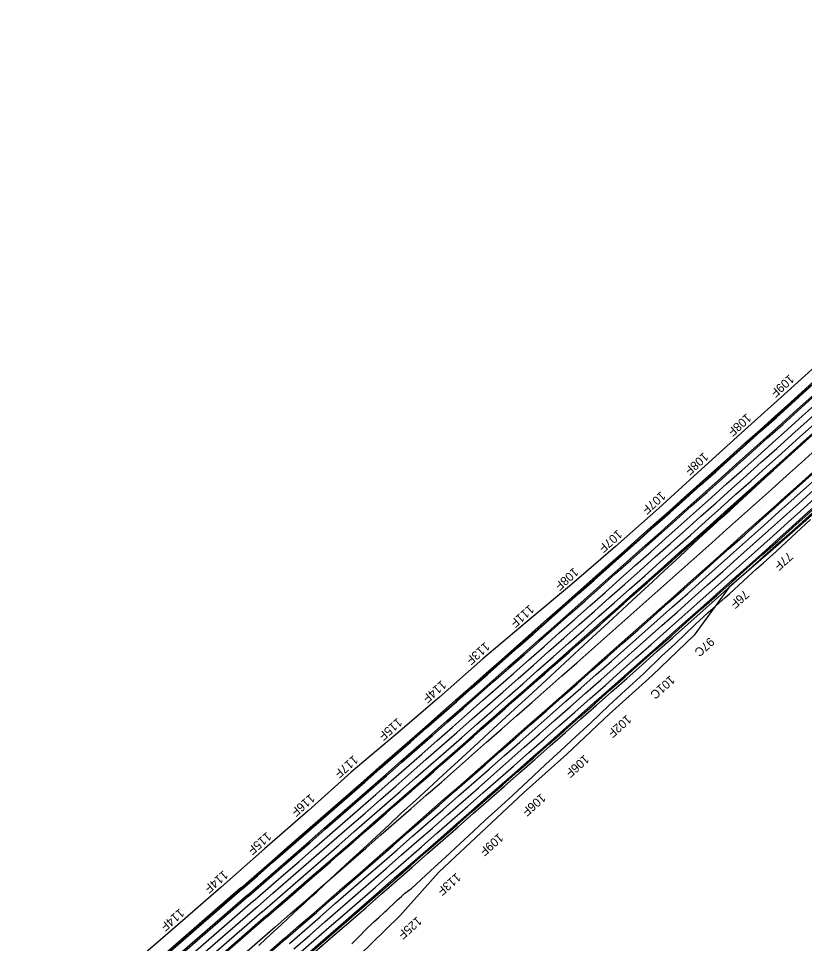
# Model space of a CAD drawing. Extents: x 2163396 to 2173129, y 605545 to 614595.
# Drawn here: x 2169556 to 2170912, y 611691 to 613286 of the extents above; entities that cross this region are included whole.
import ezdxf

# ---------------------------------------------------------------- set-up
doc = ezdxf.new("R2010")
doc.units = 0
for name, color, linetype in [('RD_PD_AsphRem', 7, 'Continuous'), ('RD_PD_CstnLmt', 7, 'Continuous'), ('RD_PD_EarthShd', 7, 'Continuous'), ('RD_PD_Final_LnLine', 7, 'Continuous'), ('RD_PD_Final_TrvlWay', 7, 'Continuous'), ('RD_PD_GR', 7, 'Continuous'), ('RD_PD_MedBWall', 7, 'Continuous'), ('RD_PD_TX_CstnLmt', 7, 'Continuous')]:
    doc.layers.add(name, color=color, linetype=linetype)

msp = doc.modelspace()

# ---------------------------------------------------------------- linework, layer by layer
at = {"layer": 'RD_PD_AsphRem'}
for points in [[(2169970.4, 611688.1), (2169983, 611699.5), (2169997.2, 611712.6), (2170008.5, 611723), (2170019.8, 611733.5), (2170031.8, 611744.5), (2170049.2, 611760.8), (2170061.5, 611772.2), (2170070.1, 611780.1), (2170083.4, 611792.3), (2170103.4, 611811.3), (2170127.9, 611833.7), (2170150.2, 611854), (2170173.7, 611876), (2170195.2, 611895.8), (2170216.4, 611915.9), (2170241.1, 611938.1), (2170263.7, 611959.3), (2170288.5, 611982.2), (2170314.6, 612005.9), (2170342.2, 612031.3), (2170367.1, 612054.4), (2170389.4, 612074.8), (2170412.4, 612095.8), (2170435.7, 612117.3), (2170458.6, 612138.6), (2170481.9, 612160), (2170507.1, 612183.4), (2170530.6, 612205), (2170552.9, 612225.7), (2170580.4, 612251), (2170606.6, 612275.4), (2170629.3, 612296.6), (2170649.7, 612315.1), (2170669.9, 612334), (2170689.8, 612352.3), (2170706.1, 612367.4), (2170720.5, 612381.2), (2170736.9, 612396.3), (2170753.8, 612411.6), (2170769.4, 612425.8), (2170782.9, 612438.2), (2170812.1, 612465), (2170836.2, 612487.5), (2170858.2, 612507.6)], [(2170858.2, 612507.6), (2170858.2, 612507.6)], [(2170131.1, 611690.6), (2170136.4, 611696), (2170145.4, 611705.4), (2170153.4, 611713.6), (2170158.7, 611718.7), (2170164.7, 611723.9), (2170167.2, 611726.7), (2170169.8, 611729), (2170176.8, 611735.6), (2170188.2, 611745.9), (2170191.5, 611748.9), (2170196.3, 611753.5), (2170202.7, 611759.6), (2170210.1, 611766.4), (2170216.6, 611772.2), (2170222.3, 611777.9), (2170230.4, 611783.9), (2170233.9, 611786.4), (2170266.8, 611816.4), (2170292.8, 611840.3), (2170317.3, 611862.9), (2170341.2, 611885.4), (2170360.9, 611903.8), (2170382.6, 611923.8), (2170408.1, 611946.8), (2170434.8, 611971.4), (2170465.3, 612000.1), (2170491.7, 612024.3), (2170516.8, 612047.9), (2170543.6, 612072.4), (2170574.5, 612101.7), (2170603, 612127.9), (2170634.6, 612157), (2170665.4, 612186.5), (2170688.6, 612208.2), (2170722.9, 612240.6), (2170745.9, 612262.1), (2170758.3, 612272.9), (2170775.1, 612287.9), (2170782.4, 612294.5), (2170813.8, 612323.5), (2170829.1, 612337.2), (2170841.3, 612347.9), (2170863.1, 612367.4), (2170897.7, 612400.1), (2170922.2, 612422.5)], [(2169984, 611736.6), (2169723.7, 611510.7), (2169722.6, 611509.8)]]:
    msp.add_lwpolyline(points, dxfattribs=at)
for radius, end in [(73072, 312.719474), (72976, 311.868675)]:
    msp.add_arc((2122152.2, 666851.2), radius, 310.953509, end, dxfattribs=at)
at = {"layer": 'RD_PD_CstnLmt'}
for p, q in [((2170956.3, 612710.4), (2170882.2, 612643.4)), ((2170882.2, 612643.4), (2170808.4, 612576.2)), ((2170808.4, 612576.2), (2170734.3, 612509.2)), ((2170734.3, 612509.2), (2170660.6, 612441.8)), ((2170660.6, 612441.8), (2170585.8, 612375.7)), ((2170933, 612437.1), (2170857.7, 612371.2)), ((2170585.8, 612375.7), (2170510.2, 612310.4)), ((2170857.7, 612371.2), (2170782.1, 612305.6)), ((2170510.2, 612310.4), (2170433.6, 612246.3)), ((2170782.1, 612305.6), (2170721.4, 612223.2)), ((2170433.6, 612246.3), (2170357.2, 612182)), ((2170721.4, 612223.2), (2170649.2, 612153.7)), ((2170357.2, 612182), (2170282.2, 612116.1)), ((2170649.2, 612153.7), (2170575, 612086.5)), ((2170282.2, 612116.1), (2170206.2, 612051.4)), ((2170575, 612086.5), (2170502.1, 612017.7)), ((2170206.2, 612051.4), (2170130.1, 611986.7)), ((2170502.1, 612017.7), (2170427.3, 611951.1)), ((2170130.1, 611986.7), (2170055.5, 611920.3)), ((2170427.3, 611951.1), (2170354.2, 611882.5)), ((2170055.5, 611920.3), (2169980.4, 611854.5)), ((2170354.2, 611882.5), (2170281, 611814.1)), ((2169980.4, 611854.5), (2169905.7, 611788.2)), ((2170281, 611814.1), (2170213.6, 611739)), ((2169905.7, 611788.2), (2169830.2, 611722.7)), ((2170213.6, 611739), (2170141.8, 611668.9)), ((2169830.2, 611722.7), (2169754.5, 611657.3))]:
    msp.add_line(p, q, dxfattribs=at)
at = {"layer": 'RD_PD_EarthShd'}
for p, q in [((2169939.9, 611787.5), (2169556.2, 611454.5)), ((2169984, 611736.6), (2169600.3, 611403.7)), ((2170015.5, 611700.4), (2169631.8, 611367.4))]:
    msp.add_line(p, q, dxfattribs=at)
for radius, end in [(72908.7, 312.719474), (73075.8, 312.719474), (72976, 312.614643), (73024, 312.612747)]:
    msp.add_arc((2122152.2, 666851.2), radius, 310.953509, end, dxfattribs=at)
at = {"layer": 'RD_PD_Final_LnLine'}
for p, q in [((2169941.8, 611785.2), (2169558.2, 611452.2)), ((2169951, 611774.7), (2169567.3, 611441.7)), ((2169960.4, 611763.8), (2169576.7, 611430.8)), ((2169968.3, 611754.8), (2169584.6, 611421.8)), ((2169976.2, 611745.7), (2169592.5, 611412.7))]:
    msp.add_line(p, q, dxfattribs=at)
for radius in [72911.7, 72925.7, 72940, 72952, 72964, 73036, 73048, 73060]:
    msp.add_arc((2122152.2, 666851.2), radius, 310.953509, 312.719474, dxfattribs=at)
at = {"layer": 'RD_PD_Final_TrvlWay'}
for p, q in [((2169941.2, 611786), (2169557.5, 611453)), ((2169982.7, 611738.2), (2169599, 611405.2)), ((2170016.8, 611698.9), (2169633.1, 611365.9))]:
    msp.add_line(p, q, dxfattribs=at)
for radius in [72910.7, 72974, 73026, 73070]:
    msp.add_arc((2122152.2, 666851.2), radius, 310.953509, 312.719474, dxfattribs=at)
at = {"layer": 'RD_PD_GR'}
msp.add_line((2169998.8, 611719.7), (2169615.1, 611386.7), dxfattribs=at)
for radius, end in [(72998.5, 312.690672), (73072, 312.719474)]:
    msp.add_arc((2122152.2, 666851.2), radius, 310.953509, end, dxfattribs=at)
at = {"layer": 'RD_PD_MedBWall'}
for p, q in [((2169951, 611774.7), (2169567.3, 611441.7)), ((2169952.6, 611772.9), (2169568.9, 611439.9))]:
    msp.add_line(p, q, dxfattribs=at)
for radius in [72925.7, 72928]:
    msp.add_arc((2122152.2, 666851.2), radius, 310.953509, 312.719474, dxfattribs=at)

# ---------------------------------------------------------------- texts
at = {"layer": 'RD_PD_TX_CstnLmt'}
for s, rotation, p in [('109F', 221.954, (2170885.7, 612673.4)), ('108F', 221.8755, (2170811.9, 612606.2)), ('108F', 221.797, (2170737.9, 612539.2)), ('107F', 221.7185, (2170664.2, 612471.8)), ('107F', 221.64, (2170589.4, 612405.7)), ('77F', 221.797, (2170883.7, 612367.6)), ('108F', 221.5615, (2170513.9, 612340.4)), ('76F', 221.7185, (2170808.1, 612301.9)), ('111F', 221.483, (2170437.4, 612276.3)), ('113F', 221.4045, (2170361, 612212)), ('97C', 221.64, (2170748.2, 612220.3)), ('114F', 221.3261, (2170286, 612146.1)), ('101C', 221.5615, (2170680.3, 612154.5)), ('115F', 221.2476, (2170210, 612081.3)), ('102F', 221.483, (2170605.2, 612086.5)), ('106F', 221.4045, (2170532.3, 612017.7)), ('117F', 221.1691, (2170134, 612016.7)), ('116F', 221.0906, (2170059.4, 611950.3)), ('106F', 221.3261, (2170457.5, 611951)), ('115F', 221.0121, (2169984.4, 611884.5)), ('109F', 221.2476, (2170384.4, 611882.4)), ('114F', 220.9535, (2169909.7, 611818.2)), ('113F', 221.1691, (2170311.3, 611814)), ('114F', 220.9535, (2169834.2, 611752.6)), ('125F', 221.0906, (2170243.8, 611738.8))]:
    msp.add_text(s, height=15, rotation=rotation, dxfattribs=at).set_placement(p)

doc.saveas('drawing.dxf')
